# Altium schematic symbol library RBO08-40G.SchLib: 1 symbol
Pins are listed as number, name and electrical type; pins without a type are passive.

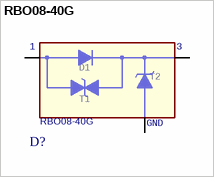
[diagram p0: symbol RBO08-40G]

## RBO08-40G
designator D?
footprint ST_D2PAK-CLIP
pins: 1, 3, TAB GND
